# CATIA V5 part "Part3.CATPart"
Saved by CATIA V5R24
Part number: Part3
Bounding box of the stored display mesh (mm): x 0 to 20, y 0 to 66.18, z -9.985 to 299.985
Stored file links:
  G:\_CAD수업\DMU_paradoxes\inversion\Part3.CATPart
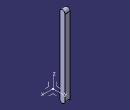
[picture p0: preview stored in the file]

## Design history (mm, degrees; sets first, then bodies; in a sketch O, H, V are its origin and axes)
AxisSystem1: origin (0, 0, 0), X (1, 0, 0), Y (0, 1, 0), Z (0, 0, 1)
Body1 (main body)
  DatumSurface1
  Sketch1 on YZ plane of AxisSystem1, origin (0, 0, 0), H (0, 1, 0), V (0, 0, 1)
    construction line L1 (56.1803, 0) -> (56.1803, 290)
    line L2 (46.1803, 0) -> (46.1803, 290)
    line L3 (66.1803, 290) -> (66.1803, 0)
    arc A1 centre (56.1803, 290) radius 10 from (46.1803, 290) to (66.1803, 290) cw
    arc A2 centre (56.1803, 0) radius 10 from (66.1803, 0) to (46.1803, 0) cw
    distance L1 L2 = 10
    vertical: L1 V
    tangency: A1 L2, A2 L2, A1 L3, A2 L3
  Pad1: profile Sketch1, direction (1, 0, 0), length 20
